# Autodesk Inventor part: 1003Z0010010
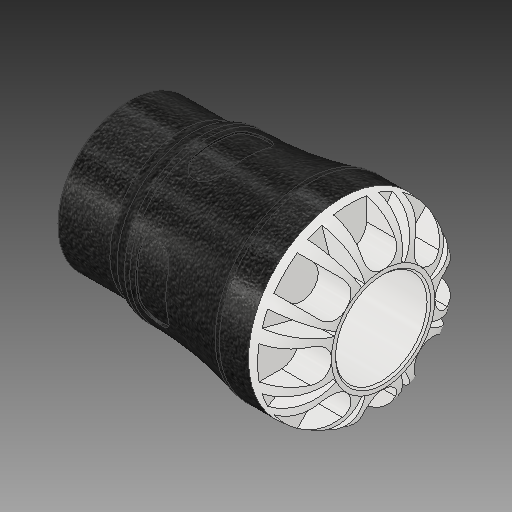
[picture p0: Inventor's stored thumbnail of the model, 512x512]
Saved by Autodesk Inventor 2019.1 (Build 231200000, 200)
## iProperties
Created: 2016-12
Part Number: 1003Z0010010
Material: PVC-Piping
Description: PLASSON FEMALE ADAPTOR 1''CTS x 1''NPT SERIES 1
Document SubType Name: Modeling
Designer: KIM
Mass: 664.23 g
Surface Area: 733.008 cm^2
Volume: 474.45 cm^3
Density: 1.4 g/cm^3
Appearance: Black Cast
Author: KIM
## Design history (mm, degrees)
derived "1003Z.ipt"
feature "Solid1::1003Z.ipt"
tag "TaggingFeature1"
body "Solid1"
other parameters: "d0" = 78.994, "d1" = 22.72284, "d2" = 28.45, "d3" = 32.13275, "d4" = 57.912, "d6" = 54.102, "d8" = 49.2252, "d13" = 10.3117, "d14" = 10.3117, "d15" = 0, "d17" = 360 deg, "d19" = 8 deg, "d20" = 0.569, "d21" = 0.569, "d22" = 8 deg, "d24" = 0, "d26" = 360 deg, "d32" = 5.7912, "d33" = 5.7912, "d39" = 0.55893, "d42" = 18.631, "d43" = 45.17136, "d46" = 2.37083, "d47" = 21.082, "d48" = 17.69945, "d50" = 1.2573, "d51" = 0.57912, "d54" = 9.9575, "d55" = 6.259, "d57" = 17.52201, "d58" = 0, "d68" = 360 deg, "d72" = 0.569, "d74" = 0, "d76" = 8.46387, "d_" = 28.45, "E_" = 57.912, "H_" = 78.994, "l_" = 54.102, "G_" = 18.631, "l_2" = 21.082, "d9" = 12.88963, "d11" = 57.912, "d12" = 32.13275, "d49" = 3.81
